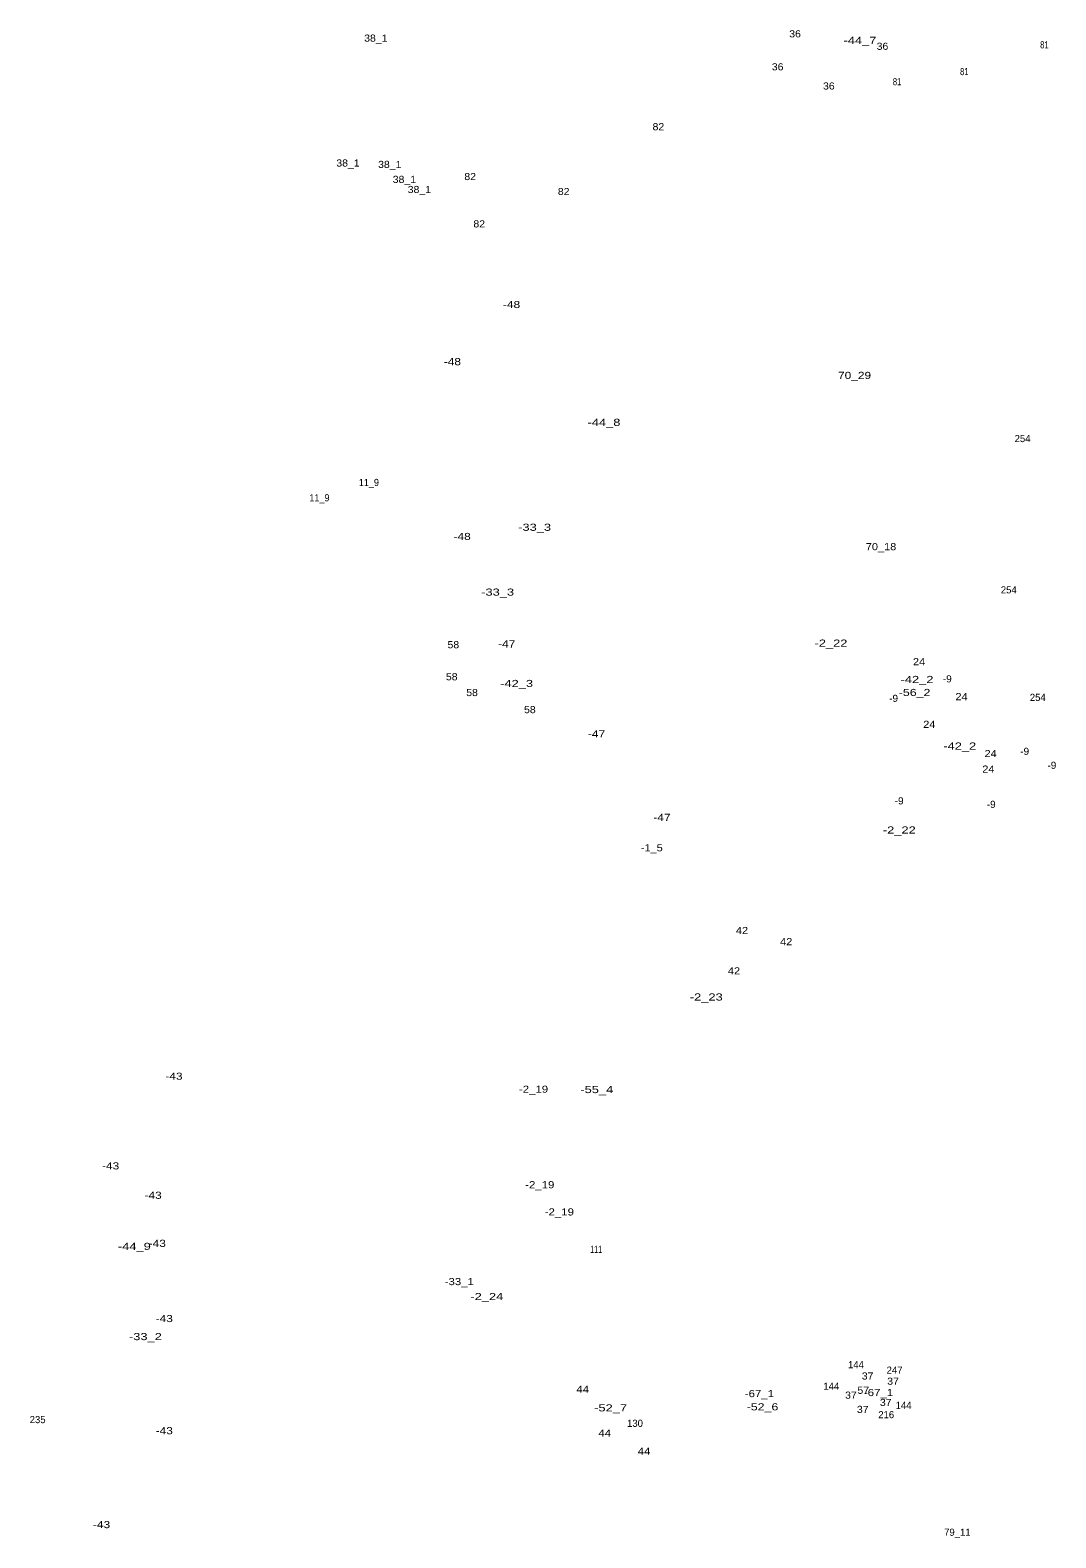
# Model space of a CAD drawing. Extents: x -659306 to -656317, y -989614 to -987663.
# Drawn here: x -659306 to -658730, y -989614 to -988767 of the extents above; entities that cross this region are included whole.
import ezdxf
from ezdxf.enums import TextEntityAlignment as Align

# ---------------------------------------------------------------- set-up
doc = ezdxf.new("R2010")
doc.units = 0
doc.header["$LTSCALE"] = 1.6
doc.layers.add('24', color=7, linetype='Continuous')

msp = doc.modelspace()

# ---------------------------------------------------------------- texts
at = {"layer": '24'}
for s, width, p in [('38_1', 1.1, (-659112.12, -988773.64)), ('36', 1.1, (-658876.72, -988771.24)), ('-44_7', 1.35, (-658840.29, -988774.93)), ('36', 1.1, (-658827.64, -988778.23)), ('81', 0.8, (-658736.72, -988777.38)), ('36', 1.1, (-658886.49, -988789.77)), ('81', 0.8, (-658781.689, -988792.44)), ('36', 1.1, (-658857.75, -988800.53)), ('81', 0.8, (-658819.429, -988798.11)), ('82', 1.1, (-658953.459, -988823.42)), ('38_1', 1.1, (-659127.76, -988843.8)), ('38_1', 1.1, (-659104.29, -988844.59)), ('38_1', 1.1, (-659096.08, -988853)), ('82', 1.1, (-659059.14, -988851.39)), ('38_1', 1.1, (-659087.67, -988858.67)), ('82', 1.1, (-659006.64, -988859.8)), ('82', 1.1, (-659054.059, -988877.99)), ('-48', 1.25, (-659035.9, -988923.29)), ('-48', 1.25, (-659069.14, -988955.37)), ('70_29', 1.25, (-658843.3, -988963.09)), ('-44_8', 1.35, (-658984.01, -988989.47)), ('11_9', 0.95, (-659116.01, -989023.22)), ('11_9', 0.95, (-659143.78, -989031.83)), ('-48', 1.25, (-659063.66, -989053.56)), ('-33_3', 1.35, (-659022.959, -989048.39)), ('70_18', 1.15, (-658828.439, -989059.27)), ('-33_3', 1.35, (-659043.709, -989084.81)), ('58', 1.1, (-659068.6, -989114.36)), ('-47', 1.25, (-659038.64, -989113.93)), ('-2_22', 1.35, (-658856.54, -989113.46)), ('24', 1.15, (-658807.079, -989123.87)), ('58', 1.1, (-659069.5, -989132.35)), ('58', 1.1, (-659058.09, -989141.23)), ('-42_3', 1.35, (-659033.06, -989136.13)), ('-56_2', 1.3, (-658809.6, -989141.18)), ('-42_2', 1.35, (-658808.23, -989133.87)), ('-9', 1.05, (-658791.24, -989133.53)), ('-9', 1.05, (-658821.39, -989144.5)), ('24', 1.15, (-658783.23, -989143.52)), ('58', 1.1, (-659025.63, -989150.82)), ('-47', 1.25, (-658988.191, -989164.46)), ('24', 1.15, (-658801.319, -989159.07)), ('-42_2', 1.35, (-658784.25, -989171.28)), ('-9', 1.05, (-658747.79, -989174.26)), ('24', 1.15, (-658766.9, -989175.5)), ('-9', 1.05, (-658732.52, -989182.1)), ('24', 1.15, (-658768.169, -989184.21)), ('-9', 1.05, (-658818.26, -989202.07)), ('-9', 1.05, (-658766.58, -989204.03)), ('-47', 1.25, (-658951.431, -989211.34)), ('-2_22', 1.35, (-658818.169, -989218.43)), ('-1_5', 1.15, (-658957.179, -989228.43)), ('42', 1.15, (-658906.52, -989274.87)), ('42', 1.15, (-658881.689, -989281.13)), ('42', 1.15, (-658911.02, -989297.56)), ('-2_23', 1.35, (-658926.559, -989312.22)), ('-43', 1.25, (-659225.45, -989356.7)), ('-2_19', 1.2, (-659023.571, -989364.01)), ('-55_4', 1.35, (-658988.05, -989364.22)), ('-43', 1.25, (-659261.03, -989407.09)), ('-2_19', 1.2, (-659020.051, -989417.67)), ('-43', 1.25, (-659237.18, -989423.59)), ('-2_19', 1.2, (-659009.081, -989432.95)), ('-44_9', 1.35, (-659247.699, -989452.3)), ('-43', 1.25, (-659234.83, -989450.59)), ('111', 0.6, (-658988.42, -989453.96)), ('-33_1', 1.2, (-659065.25, -989472.08)), ('-2_24', 1.35, (-659049.79, -989480.47)), ('-43', 1.25, (-659230.92, -989492.83)), ('-33_2', 1.35, (-659241.51, -989502.97)), ('37', 1.1, (-658835.97, -989525.09)), ('37', 1.1, (-658821.69, -989528.02)), ('44', 1.2, (-658995.92, -989532.56)), ('-67_1', 1.2, (-658896.72, -989534.99)), ('37', 1.1, (-658845.35, -989535.85)), ('57', 1.1, (-658838.41, -989533.13)), ('-67_1', 1.2, (-658829.85, -989534.41)), ('-52_7', 1.35, (-658980.3, -989543.01)), ('-52_6', 1.3, (-658895.01, -989542.42)), ('37', 1.1, (-658838.7, -989543.87)), ('37', 1.1, (-658825.8, -989539.95)), ('-43', 1.25, (-659230.92, -989555.82)), ('44', 1.2, (-658983.6, -989557.21)), ('44', 1.2, (-658961.51, -989567.38)), ('-43', 1.25, (-659266.12, -989608.57))]:
    msp.add_text(s, height=4, dxfattribs=dict(at, width=width)).set_placement(p, align=Align.CENTER)
for s, p in [('254', (-658748.981, -988998.57)), ('254', (-658756.721, -989083.54)), ('254', (-658740.431, -989143.93)), ('144', (-658842.49, -989518.73)), ('247', (-658820.857, -989521.82)), ('144', (-658856.37, -989530.86)), ('216', (-658825.541, -989546.82)), ('144', (-658815.8, -989541.62)), ('235', (-659302.017, -989549.6)), ('130', (-658966.59, -989551.68)), ('79_11', (-658785.581, -989612.86))]:
    msp.add_text(s, height=4, dxfattribs=at).set_placement(p, align=Align.CENTER)

doc.saveas('drawing.dxf')
